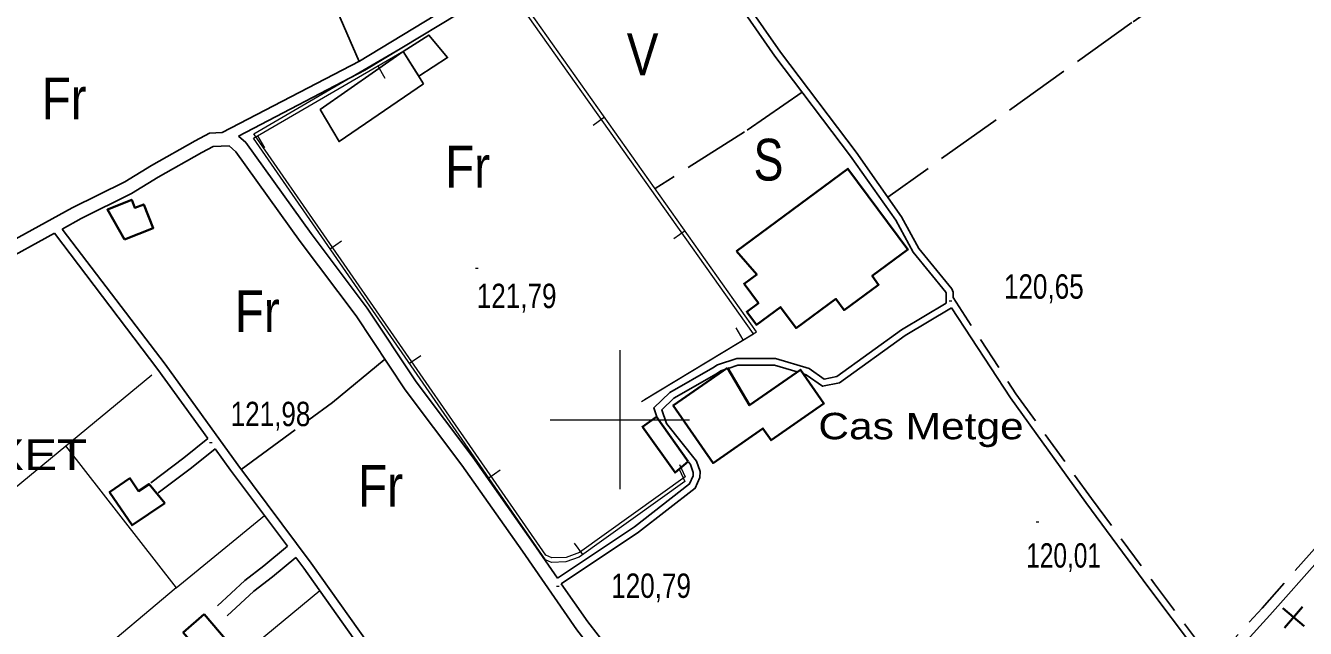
# Model space of a CAD drawing. Extents: x 483855 to 488461, y 4388206 to 4391419.
# Drawn here: x 485786.6 to 486246.1, y 4389425 to 4389641.6 of the extents above; entities that cross this region are included whole.
import ezdxf
from ezdxf.enums import TextEntityAlignment as Align

# ---------------------------------------------------------------- set-up
doc = ezdxf.new("R2010")
doc.units = 0
doc.header["$LTSCALE"] = 4
doc.linetypes.add('LONG_DASHED', pattern=[7.5, 6, -1.5])
doc.linetypes.add('MEDIUM_DASHED', pattern=[4.5, 3, -1.5])
for name, color, linetype, lineweight in [('1', 7, 'Continuous', 13), ('21', 7, 'Continuous', 25), ('24', 7, 'Continuous', 13), ('25', 7, 'LONG_DASHED', 25), ('34', 7, 'Continuous', 35), ('38', 7, 'Continuous', 25), ('47', 7, 'Continuous', 35), ('51', 7, 'Continuous', 13), ('7', 7, 'Continuous', 13)]:
    doc.layers.add(name, color=color, linetype=linetype, lineweight=lineweight)
doc.layers.add('31', color=7, linetype='Continuous')
doc.layers.add('5', color=7, linetype='Continuous')

msp = doc.modelspace()

# ---------------------------------------------------------------- linework, layer by layer
at = {"layer": '1'}
for p, q in [((486000, 4389525), (486000, 4389475)), ((485975, 4389500), (486025, 4389500))]:
    msp.add_line(p, q, dxfattribs=at)
at = {"layer": '21'}
for points in [[(485922.14, 4389632.21), (485931.43, 4389638.16), (485938.12, 4389630.07), (485927.78, 4389623.39)], [(485929.51, 4389620.67), (485899.16, 4389599.92), (485892.39, 4389611.39), (485922.14, 4389632.21)]]:
    msp.add_lwpolyline(points, close=True, dxfattribs=at)
at = {"layer": '24'}
for p, q in [((485913.09, 4389627.05), (485915.61, 4389622.73)), ((485994.51, 4389608.62), (485990.43, 4389605.73)), ((485869.87, 4389601.92), (485872.38, 4389597.6)), ((486023.42, 4389567.82), (486019.34, 4389564.93)), ((485895.91, 4389561.37), (485900.02, 4389564.21)), ((486044.28, 4389528.7), (486041.69, 4389532.98)), ((485924.39, 4389520.27), (485928.5, 4389523.12)), ((485952.87, 4389479.17), (485956.98, 4389482.02)), ((485986.64, 4389451.54), (485983.73, 4389455.61))]:
    msp.add_line(p, q, dxfattribs=at)
for points in [[(486007.68, 4389506.5), (486047.93, 4389530.79), (485964.46, 4389648.61)], [(486008.83, 4389507.31), (486049.08, 4389531.6), (485965.61, 4389649.42)], [(486021.28, 4389482.29), (486023.28, 4389477.78), (485985.37, 4389450.63), (485980.57, 4389448.9), (485975.47, 4389448.74), (485973.29, 4389449.71), (485868.4, 4389601.07), (485923.83, 4389633.29)], [(486021.37, 4389483.96), (486023.37, 4389479.45), (485985.46, 4389452.3), (485980.66, 4389450.57), (485975.56, 4389450.41), (485973.38, 4389451.38), (485868.49, 4389602.74), (485923.92, 4389634.96)]]:
    msp.add_lwpolyline(points, dxfattribs=at)
at = {"layer": '25'}
for points in [[(486499.22, 4389863.86), (486375.28, 4389778.03), (486183.84, 4389642.62), (486096.17, 4389579.94)], [(485757.52, 4389652.8), (485873.49, 4389704), (485906.34, 4389628.7)], [(486065.39, 4389617.68), (486044.76, 4389603.39), (486012.65, 4389583.04)], [(485864.04, 4389482.17), (485896.84, 4389506.22), (485915.63, 4389521.68)]]:
    msp.add_lwpolyline(points, dxfattribs=at)
at = {"layer": '34'}
for p, q in [((486245.68, 4389425.81), (486238.05, 4389432.26)), ((486238.64, 4389425.22), (486245.09, 4389432.85))]:
    msp.add_line(p, q, dxfattribs=at)
at = {"layer": '38'}
for points in [[(486119.59, 4389543.88), (486119.59, 4389545.85), (486119.21, 4389546.97), (486107.31, 4389561.53), (486101.12, 4389572.93), (486084.76, 4389596.05), (486057.62, 4389632.01), (486032.43, 4389668.28), (486024.35, 4389679.54), (486019.29, 4389684.36), (486015.88, 4389684.96), (486007.09, 4389683.5), (486005.3, 4389682.46), (486003.92, 4389681.43), (486002.21, 4389681.6), (486000.74, 4389682.49), (485997.22, 4389685.83), (485995.16, 4389695.99), (485982.18, 4389719.45), (485963.36, 4389761.6), (485943.18, 4389803.05), (485922.7, 4389849.38), (485904.18, 4389889.33), (485886.19, 4389928.23)], [(485602.07, 4389706.42), (485607.96, 4389696.98), (485626.08, 4389667.76), (485637.86, 4389649.03), (485652.1, 4389629.47), (485664.67, 4389610.97), (485678.43, 4389589.08), (485685.73, 4389575.16), (485698.03, 4389552.72), (485701.44, 4389547.41), (485705.34, 4389542.97), (485710.36, 4389539.88), (485716.12, 4389537.42), (485723.6, 4389537.36), (485729.19, 4389537.37), (485743.55, 4389542.02), (485774.52, 4389560.29), (485803.37, 4389576.09), (485822.28, 4389585.46), (485831.75, 4389591.25), (485847.53, 4389600.2), (485852.61, 4389602.93), (485857.22, 4389603.13)], [(485857.22, 4389603.13), (485906.54, 4389628.81), (485953.3, 4389657.25), (485987.33, 4389676.2), (485997.7, 4389682)], [(485863.02, 4389601.86), (485908.41, 4389625.49), (485955.22, 4389653.96), (485989.19, 4389672.88), (486000.94, 4389679.45)], [(486013.27, 4389501), (486012.16, 4389504.21), (486017.86, 4389509.74), (486033.39, 4389518.59), (486035.08, 4389519.75), (486041.98, 4389522.01), (486055.86, 4389522.03), (486067.99, 4389518.39), (486073.31, 4389514.61), (486077.82, 4389515.5), (486101.11, 4389532.32), (486117.09, 4389541.88), (486117.15, 4389542.21), (486117.15, 4389545.44), (486117.04, 4389545.76), (486105.27, 4389560.16), (486099.04, 4389571.64), (486082.79, 4389594.61), (486055.64, 4389630.58), (486030.43, 4389666.87)], [(485863.02, 4389601.86), (485865.66, 4389599.55), (485889.11, 4389566.85), (485909.23, 4389540.1), (485926.83, 4389513.58), (485947.16, 4389486.51), (485968.95, 4389455.56), (485977.56, 4389443.12)], [(486024.74, 4389370.21), (486006.84, 4389395.76), (485984.51, 4389424.53), (485964.96, 4389452.78), (485943.23, 4389483.65), (485922.86, 4389510.77), (485905.26, 4389537.29), (485885.19, 4389563.97), (485862.03, 4389596.26), (485859.63, 4389598.36), (485853.93, 4389598.12), (485849.88, 4389595.94), (485834.22, 4389587.06), (485824.63, 4389581.2), (485806.56, 4389572.24), (485799.7, 4389568.49)], [(485799.7, 4389568.49), (485836.7, 4389519.95), (485862.8, 4389483.83), (485889.12, 4389448.53), (485912.89, 4389414.95), (485933.86, 4389386.49), (485954.6, 4389357.77), (485956.56, 4389354.67)], [(485797.02, 4389567.02), (485776.81, 4389555.99), (485745.56, 4389537.56), (485729.96, 4389532.51), (485723.59, 4389532.5), (485715.11, 4389532.56), (485707.6, 4389535.77), (485701.75, 4389540.41), (485695.89, 4389545.66)], [(485797.02, 4389567.02), (485834.12, 4389518.03), (485852.03, 4389493.23)], [(486065.9, 4389516.46), (486066.9, 4389516.16), (486072.75, 4389512.01), (486078.82, 4389513.21), (486102.46, 4389530.28), (486119.05, 4389540.2)], [(486119.05, 4389540.2), (486140.18, 4389507.9), (486167.32, 4389470.21), (486189.95, 4389439.64), (486206.27, 4389417.84), (486212.26, 4389412.16)], [(485978.95, 4389441.1), (486006.68, 4389459.59), (486027.04, 4389475.39), (486028.65, 4389479.3), (486028.77, 4389481.45), (486027.5, 4389485.09), (486016.67, 4389498.65), (486014.98, 4389503.54), (486019.34, 4389507.77), (486034.69, 4389516.52), (486036.17, 4389517.54), (486037.6, 4389518.01)], [(486038.86, 4389518.42), (486042.37, 4389519.57), (486055.5, 4389519.59), (486063.58, 4389517.16)], [(485831.51, 4389477.34), (485843.44, 4389486.32), (485852.03, 4389493.23)], [(485834.21, 4389473.75), (485846.2, 4389482.77), (485854.67, 4389489.59)], [(485854.67, 4389489.59), (485860.21, 4389481.92), (485880.6, 4389454.57)], [(485977.56, 4389443.12), (486005.25, 4389461.57), (486025.03, 4389476.92), (486026.23, 4389479.85), (486026.3, 4389481.1), (486025.33, 4389483.89), (486024.58, 4389484.83)], [(485855.49, 4389433.19), (485865.27, 4389442.3), (485872.12, 4389447.5), (485880.6, 4389454.57)], [(485858.93, 4389429.5), (485868.52, 4389438.44), (485875.26, 4389443.55), (485883.62, 4389450.53)], [(485883.62, 4389450.53), (485886.52, 4389446.63), (485910.28, 4389413.06), (485931.26, 4389384.59), (485933.85, 4389381)], [(486223.9, 4389419.34), (486233.4, 4389429.81), (486251.36, 4389450.18)], [(485978.95, 4389441.1), (485988.43, 4389427.41), (486010.76, 4389398.65), (486031.45, 4389369.11), (486049.14, 4389345.94), (486065.95, 4389323.47), (486073.03, 4389313.47), (486083.3, 4389298.05), (486086, 4389293.94), (486088.76, 4389292.28), (486090.02, 4389291.99), (486093.4, 4389291.99), (486095.85, 4389292.17)]]:
    msp.add_lwpolyline(points, dxfattribs=at)
at = {"layer": '38', "linetype": 'MEDIUM_DASHED'}
for points in [[(486119.59, 4389543.88), (486142.2, 4389509.29), (486169.3, 4389471.65), (486191.92, 4389441.1), (486208.11, 4389419.48), (486213.84, 4389413.96)], [(486213.84, 4389413.96), (486230.58, 4389432.34), (486255.81, 4389460.96), (486278.74, 4389486.07), (486301.05, 4389508.18), (486303.29, 4389516.87), (486317.4, 4389530.87), (486323.7, 4389534.6), (486328.44, 4389534.44), (486331.87, 4389530.89), (486339, 4389516.32), (486352.8, 4389492.97), (486373.11, 4389461.14), (486384.24, 4389438.22), (486399.13, 4389415.41), (486410.7, 4389395.54), (486416.11, 4389386.23)]]:
    msp.add_lwpolyline(points, dxfattribs=at)
at = {"layer": '47'}
for points in [[(486041.9, 4389560.55), (486081.84, 4389590.17), (486103.38, 4389561.11), (486090.57, 4389551.63), (486092.87, 4389548.5), (486080.47, 4389539.4), (486077.52, 4389543.41), (486063.23, 4389532.89), (486057.67, 4389540.43), (486049.01, 4389534.06), (486045.53, 4389538.78), (486049.71, 4389541.86), (486044.56, 4389548.83), (486049.09, 4389552.19)], [(485822.1, 4389564.69), (485832.45, 4389568.83), (485829.04, 4389577.34), (485825.85, 4389576.07), (485824.68, 4389578.98), (485815.98, 4389575.48)], [(486038.59, 4389518.61), (486019.11, 4389505.07), (486033.45, 4389484.42), (486051.36, 4389496.86), (486054.29, 4389492.63), (486073.26, 4389505.79), (486064.83, 4389517.93), (486046.46, 4389505.18)], [(486024.55, 4389485.05), (486013.12, 4389501.09), (486008.06, 4389497.48), (486019.78, 4389481.03)], [(485836.59, 4389470.04), (485824.82, 4389462.07), (485816.74, 4389473.99), (485824.06, 4389478.95), (485827.17, 4389474.34), (485830.93, 4389476.89)], [(485850.68, 4389430.16), (485859.02, 4389420.42), (485850.16, 4389412.85), (485846.68, 4389416.9), (485847.96, 4389418), (485843.17, 4389423.56)]]:
    msp.add_lwpolyline(points, close=True, dxfattribs=at)
at = {"layer": '51'}
for points in [[(485721.77, 4389497.09), (485758.97, 4389455.96), (485831.93, 4389516.17)], [(485800.95, 4389490.6), (485840.69, 4389439.6), (485872.38, 4389465.6)], [(485840.69, 4389439.6), (485747.5, 4389361.28), (485747.73, 4389358.28), (485754.49, 4389351.99), (485757.26, 4389352.14)], [(485768.19, 4389332.17), (485829.9, 4389387.07), (485892.18, 4389438.64)]]:
    msp.add_lwpolyline(points, dxfattribs=at)
at = {"layer": '7'}
for p, q in [((485948.09, 4389554.47), (485949.09, 4389554.47)), ((486118.17, 4389542.67), (486119.17, 4389542.67)), ((485852.63, 4389491.83), (485853.63, 4389491.83)), ((486149.43, 4389463.28), (486150.43, 4389463.28)), ((485977.16, 4389440.27), (485978.16, 4389440.27))]:
    msp.add_line(p, q, dxfattribs=at)

# ---------------------------------------------------------------- texts
at = {"layer": '31'}
for s, width, p in [('V', 0.85, (486008.13, 4389623.75)), ('Fr', 0.85, (485800.45, 4389607.91)), ('S', 0.8, (486053.33, 4389585.91)), ('Fr', 0.85, (485945.31, 4389583.38)), ('Fr', 0.85, (485869.78, 4389531.47)), ('Fr', 0.85, (485914.05, 4389468.72))]:
    msp.add_text(s, height=15, dxfattribs=dict(at, width=width)).set_placement(p, align=Align.CENTER)
at = {"layer": '5', "width": 1.2}
for s, height, p in [('Cas Metge', 9.5, (486144.95, 4389492.97)), ('ES PUTXET', 11, (485808.63, 4389481.9))]:
    msp.add_text(s, height=height, dxfattribs=at).set_placement(p, align=Align.RIGHT)
at = {"layer": '7'}
for s, width, p in [('120,65', 0.8, (486137.88, 4389543.47)), ('121,79', 0.8, (485948.59, 4389540.1)), ('121,98', 0.8, (485860.21, 4389497.69)), ('120,01', 0.75, (486145.88, 4389446.89)), ('120,79', 0.8, (485996.87, 4389436.01))]:
    msp.add_text(s, height=8.75, dxfattribs=dict(at, width=width)).set_placement(p)

doc.saveas('drawing.dxf')
